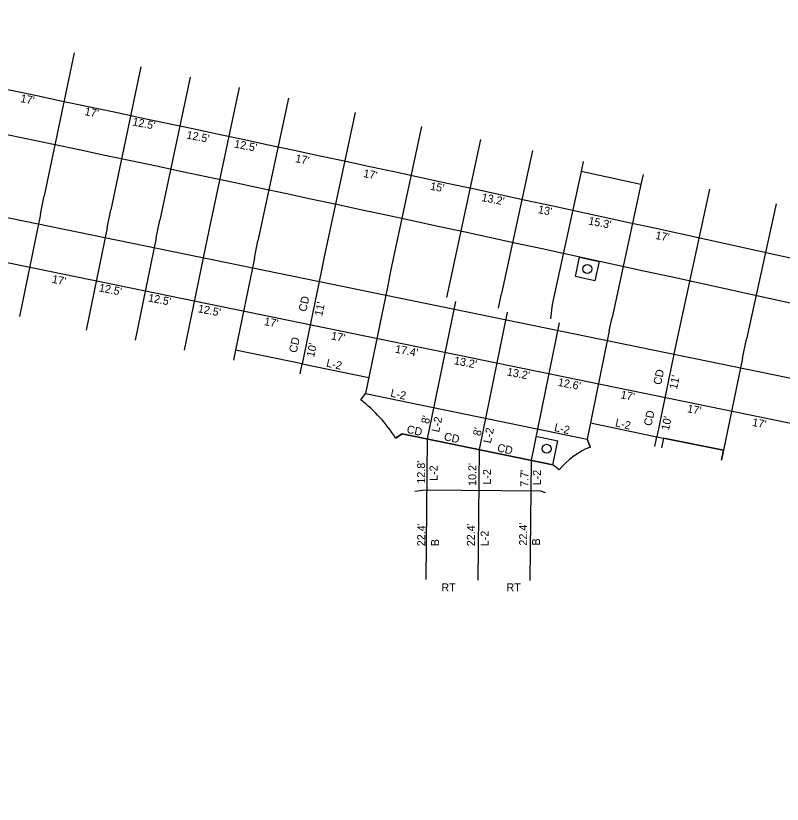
# Model space of a CAD drawing. Extents: x 4995357 to 4999033, y 3881202 to 3881750.
# Drawn here: x 4997764.8 to 4997956.4, y 3881461.9 to 3881658.9 of the extents above; entities that cross this region are included whole.
import ezdxf

# ---------------------------------------------------------------- set-up
doc = ezdxf.new("R2010")
doc.units = 0
for name, color, linetype in [('dsn3DCenterLine', 7, 'Continuous'), ('dsn3DCurbFormgrade', 7, 'Continuous'), ('dsn3DCurbTop', 7, 'Continuous'), ('dsn3DDNC', 7, 'Continuous'), ('dsn3DExistingPvmtBtm', 7, 'Continuous'), ('dsn3DIntakeWell', 7, 'Continuous')]:
    doc.layers.add(name, color=color, linetype=linetype)

msp = doc.modelspace()

# ---------------------------------------------------------------- linework, layer by layer
at = {"layer": 'dsn3DCurbFormgrade'}
for p, q in [((4997771, 3881609.31), (4997765.77, 3881583.8)), ((4997787.65, 3881605.9), (4997782.43, 3881580.39)), ((4997799.93, 3881603.39), (4997794.7, 3881577.87)), ((4997812.2, 3881600.87), (4997806.97, 3881575.36)), ((4997824.47, 3881598.36), (4997819.76, 3881575.33)), ((4997841.13, 3881594.94), (4997836.41, 3881571.92)), ((4997857.78, 3881591.53), (4997852.25, 3881564.52)), ((4997874.69, 3881587.48), (4997867.67, 3881553.19)), ((4997887.67, 3881584.82), (4997880.64, 3881550.53)), ((4997900.64, 3881582.16), (4997893.62, 3881547.87)), ((4997913.15, 3881580.19), (4997907.61, 3881553.17)), ((4997929.8, 3881576.77), (4997925.08, 3881553.75)), ((4997946.45, 3881573.36), (4997941.74, 3881550.34)), ((4997861.43, 3881554.47), (4997899.08, 3881546.75)), ((4997896.06, 3881540.14), (4997866.58, 3881540.43))]:
    msp.add_line(p, q, dxfattribs=at)
at = {"layer": 'dsn3DCurbTop'}
for p, q in [((4997779.46, 3881649.66), (4997771.95, 3881613.94)), ((4997796.13, 3881646.14), (4997788.58, 3881610.43)), ((4997808.41, 3881643.54), (4997800.84, 3881607.84)), ((4997820.69, 3881640.94), (4997813.09, 3881605.24)), ((4997832.96, 3881638.32), (4997825.35, 3881602.63)), ((4997849.62, 3881634.76), (4997841.97, 3881599.07)), ((4997866.27, 3881631.19), (4997858.6, 3881595.51)), ((4997880.99, 3881628.02), (4997873.29, 3881592.34)), ((4997893.96, 3881625.22), (4997886.24, 3881589.54)), ((4997906.11, 3881620.03), (4997898.89, 3881586.8)), ((4997921.08, 3881616.76), (4997913.84, 3881583.55)), ((4997771, 3881609.31), (4997771.95, 3881613.94)), ((4997938.24, 3881615.58), (4997930.59, 3881580.63)), ((4997954.86, 3881611.93), (4997947.42, 3881578.1)), ((4997787.65, 3881605.9), (4997788.58, 3881610.43)), ((4997799.93, 3881603.39), (4997800.84, 3881607.84)), ((4997813.09, 3881605.24), (4997812.2, 3881600.87)), ((4997824.47, 3881598.36), (4997825.35, 3881602.63)), ((4997841.97, 3881599.07), (4997841.13, 3881594.94)), ((4997858.6, 3881595.51), (4997857.78, 3881591.53)), ((4997873.29, 3881592.33), (4997872.51, 3881588.51)), ((4997885.48, 3881585.86), (4997886.24, 3881589.54)), ((4997898.89, 3881586.8), (4997898.45, 3881583.2)), ((4997913.15, 3881580.19), (4997913.84, 3881583.55)), ((4997930.59, 3881580.63), (4997929.8, 3881576.77)), ((4997946.45, 3881573.36), (4997947.42, 3881578.1)), ((4997851.04, 3881562.92), (4997852.25, 3881564.52)), ((4997859.73, 3881553.41), (4997861.43, 3881554.47)), ((4997908.42, 3881551.18), (4997907.61, 3881553.17)), ((4997900.62, 3881545.47), (4997899.08, 3881546.75)), ((4997864.6, 3881540.13), (4997866.58, 3881540.43)), ((4997897.25, 3881539.7), (4997896.06, 3881540.14))]:
    msp.add_line(p, q, dxfattribs=at)
at = {"layer": 'dsn3DDNC'}
for p, q in [((4997658.03, 3881629.91), (4998165.9, 3881525.84)), ((4997655.82, 3881619.13), (4998163.69, 3881515.07)), ((4997836.41, 3881571.92), (4997853.06, 3881568.51)), ((4997852.25, 3881564.52), (4997907.61, 3881553.17)), ((4997908.43, 3881557.17), (4997925.08, 3881553.75)), ((4997867.67, 3881553.19), (4997867.32, 3881518.05)), ((4997880.64, 3881550.53), (4997880.32, 3881517.92)), ((4997893.62, 3881547.87), (4997893.32, 3881517.79))]:
    msp.add_line(p, q, dxfattribs=at)
for radius in [20000, 19989]:
    msp.add_arc((4993658.81, 3862065.98), radius, 76.008501, 78.420039, dxfattribs=at)
at = {"layer": 'dsn3DExistingPvmtBtm'}
for p, q in [((4997906.64, 3881622.47), (4997906.11, 3881620.03)), ((4997921.08, 3881616.76), (4997906.11, 3881620.02)), ((4997921.61, 3881619.21), (4997921.08, 3881616.76)), ((4997819.76, 3881575.33), (4997819.25, 3881572.89)), ((4997836.41, 3881571.92), (4997819.76, 3881575.33)), ((4997835.91, 3881569.47), (4997836.41, 3881571.92)), ((4997894.84, 3881553.84), (4997900.3, 3881552.72)), ((4997899.08, 3881546.75), (4997900.3, 3881552.72)), ((4997924.58, 3881551.3), (4997925.08, 3881553.75)), ((4997925.08, 3881553.75), (4997941.74, 3881550.34)), ((4997941.74, 3881550.34), (4997941.24, 3881547.89))]:
    msp.add_line(p, q, dxfattribs=at)
msp.add_lwpolyline([(4997909.57, 3881592.66), (4997904.68, 3881593.73), (4997905.74, 3881598.61), (4997910.63, 3881597.55)], close=True, dxfattribs=at)
msp.add_lwpolyline([(4997941.24, 3881547.89), (4997941.74, 3881550.34), (4997926.72, 3881553.42), (4997926.21, 3881550.97)], dxfattribs=at)
for centre in [(4997907.65, 3881595.64), (4997897.5, 3881550.72)]:
    msp.add_circle(centre, 1.12, dxfattribs=at)
at = {"layer": 'dsn3DIntakeWell'}
for points in [[(4997851.04, 3881562.92), (4997852.25, 3881564.52), (4997907.61, 3881553.17), (4997908.42, 3881551.18)], [(4997900.62, 3881545.47), (4997899.08, 3881546.75), (4997861.43, 3881554.47), (4997859.73, 3881553.41)]]:
    msp.add_lwpolyline(points, dxfattribs=at)
for centre, radius, start, end in [((4997829.99, 3881534.96), 35, 31.8211, 53.0176), ((4997915.97, 3881532.65), 20, 112.1632, 140.1414)]:
    msp.add_arc(centre, radius, start, end, dxfattribs=at)

# ---------------------------------------------------------------- texts
at = {"layer": 'dsn3DCenterLine'}
for s, rotation, p in [("17'", 349.171, (4997765.9, 3881637.36)), ("17'", 349.171, (4997781.93, 3881634.09)), ("12.5'", 349.171, (4997793.88, 3881631.52)), ("12.5'", 349.171, (4997807.4, 3881628.24)), ("12.5'", 349.171, (4997819.31, 3881626)), ("17'", 349.171, (4997834.58, 3881622.35)), ("17'", 349.171, (4997851.58, 3881618.63)), ("15'", 349.171, (4997868.29, 3881615.45)), ("13.2'", 349.171, (4997881.13, 3881612.63)), ("13'", 349.171, (4997895.22, 3881609.62)), ("15.3'", 349.171, (4997907.82, 3881606.76)), ("17'", 349.171, (4997924.57, 3881603.16)), ("17'", 349.171, (4997773.78, 3881592.21)), ("12.5'", 349.171, (4997785.51, 3881590.06)), ("12.5'", 349.171, (4997797.8, 3881587.55)), ('CD', 77.6448, (4997837.42, 3881584.85)), ("12.5'", 349.171, (4997810.25, 3881584.85)), ("11'", 77.6448, (4997841.4, 3881583.74)), ("17'", 349.171, (4997826.81, 3881581.65)), ('CD', 77.6448, (4997835.03, 3881574.59)), ("17'", 349.171, (4997843.53, 3881578.06)), ("10'", 77.6448, (4997839.39, 3881573.47)), ("17.4'", 349.171, (4997859.52, 3881574.77)), ('L-2', 347.4627, (4997842.31, 3881571.29)), ("13.2'", 349.171, (4997874.23, 3881571.86)), ("13.2'", 349.171, (4997887.46, 3881569.06)), ('CD', 77.6448, (4997926.07, 3881566.56)), ("11'", 77.6448, (4997930.05, 3881565.45)), ("12.6'", 349.171, (4997900.2, 3881566.47)), ('L-2', 347.4627, (4997858.35, 3881563.79)), ("17'", 349.171, (4997915.87, 3881563.34)), ("17'", 349.171, (4997932.51, 3881559.87)), ("8'", 77.6448, (4997868.07, 3881556.83)), ('L-2', 77.6448, (4997870.62, 3881554.72)), ('CD', 77.6448, (4997923.68, 3881556.3)), ("10'", 77.6448, (4997928.04, 3881555.18)), ('L-2', 347.4627, (4997899.27, 3881555.2)), ('L-2', 347.4627, (4997914.51, 3881556.35)), ("17'", 349.171, (4997948.76, 3881556.47)), ('CD', 347.4627, (4997862.41, 3881554.73)), ('CD', 347.4627, (4997871.72, 3881552.92)), ("8'", 77.6448, (4997881, 3881553.81)), ('L-2', 77.6448, (4997883.55, 3881551.97)), ('CD', 347.4627, (4997885.02, 3881550.1)), ("12.8'", 90, (4997867.13, 3881542.03)), ("10.2'", 90, (4997879.93, 3881541.46)), ('L-2', 90, (4997870.24, 3881542.71)), ('L-2', 90, (4997883.6, 3881541.78)), ("7.7'", 90, (4997892.97, 3881541.23)), ('L-2', 90, (4997896.08, 3881541.6)), ("22.4'", 90, (4997867.17, 3881526.39)), ("22.4'", 90, (4997879.57, 3881526.39)), ("22.4'", 90, (4997892.62, 3881526.56)), ('L-2', 90, (4997883, 3881526.39)), ('B', 90, (4997870.62, 3881526.39)), ('B', 90, (4997895.85, 3881526.56))]:
    msp.add_text(s, height=2, rotation=rotation, dxfattribs=at).set_placement(p)
for p in [(4997871.22, 3881515.11), (4997887.48, 3881515.11)]:
    msp.add_text('RT', height=2, dxfattribs=at).set_placement(p)

doc.saveas('drawing.dxf')
